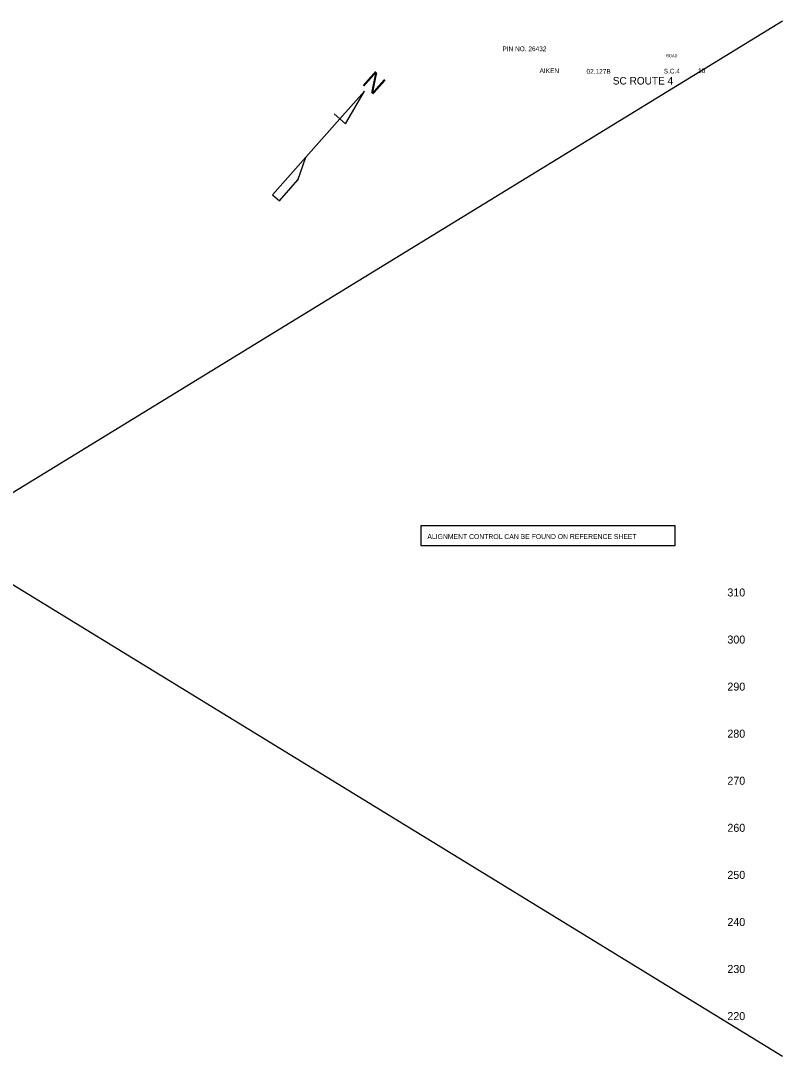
# Model space of a CAD drawing. Extents: x 49241 to 62599, y 49216 to 56011.
# Drawn here: x 51047 to 51856, y 53788 to 54888 of the extents above; entities that cross this region are included whole.
import ezdxf

# ---------------------------------------------------------------- set-up
doc = ezdxf.new("R2010")
doc.units = 0
for name, color, linetype in [('Level 1', 7, 'Continuous'), ('Level 2', 7, 'Continuous'), ('Level 24', 7, 'Continuous'), ('Level 25', 7, 'Continuous'), ('Level 42', 7, 'Continuous')]:
    doc.layers.add(name, color=color, linetype=linetype)

msp = doc.modelspace()

# ---------------------------------------------------------------- linework, layer by layer
at = {"layer": 'Level 1'}
for p, q in [((50060.6, 53787.8), (51856.5, 54887.8)), ((50060.6, 54887.8), (51856.5, 53787.8))]:
    msp.add_line(p, q, dxfattribs=at)
at = {"layer": 'Level 2'}
for p, q in [((51412.3, 54812.8), (51386.3, 54783.5)), ((51392.1, 54778.3), (51412.3, 54812.8)), ((51412.3, 54812.8), (51412.3, 54812.8)), ((51350.1, 54742.8), (51386.3, 54783.5)), ((51380.4, 54788.7), (51386.3, 54783.5)), ((51386.3, 54783.5), (51392.1, 54778.3)), ((51392.1, 54778.3), (51392.4, 54778.6)), ((51350.1, 54742.8), (51314.6, 54702.9)), ((51341.5, 54718.4), (51350.1, 54742.8)), ((51322, 54696.4), (51341.7, 54718.6)), ((51341.7, 54718.6), (51341.5, 54718.4)), ((51314.6, 54702.9), (51322, 54696.4))]:
    msp.add_line(p, q, dxfattribs=at)
at = {"layer": 'Level 25'}
msp.add_lwpolyline([(51472.8, 54351.4), (51742.2, 54351.4), (51742.2, 54330.1), (51472.8, 54330.1)], close=True, dxfattribs=at)

# ---------------------------------------------------------------- texts
at = {"layer": 'Level 2'}
msp.add_text('N', height=20, rotation=318.3667, dxfattribs=at).set_placement((51408.9, 54820.8))
at = {"layer": 'Level 24'}
for s, height, p in [('PIN NO. 26432', 5, (51559, 54855.4)), ('ROAD', 3, (51733, 54849)), ('AIKEN', 5, (51598.5, 54832.1)), ('02.127B', 5, (51648.4, 54831.4)), ('S.C.4', 5, (51730.4, 54831.7)), ('10', 5, (51766.9, 54832.2)), ('SC ROUTE 4', 8, (51676.3, 54820))]:
    msp.add_text(s, height=height, dxfattribs=at).set_placement(p)
at = {"layer": 'Level 25'}
msp.add_text('ALIGNMENT CONTROL CAN BE FOUND ON REFERENCE SHEET', height=5.25, dxfattribs=at).set_placement((51479.3, 54337.2))
at = {"layer": 'Level 42'}
for s, p in [('310', (51798.1, 54276.2)), ('300', (51798.1, 54226.2)), ('290', (51798.1, 54176.2)), ('280', (51798.1, 54126.2)), ('270', (51798.1, 54076.2)), ('260', (51798.1, 54026.2)), ('250', (51798.1, 53976.2)), ('240', (51798.1, 53926.2)), ('230', (51798.1, 53876.2)), ('220', (51798.1, 53826.2))]:
    msp.add_text(s, height=8.5, dxfattribs=at).set_placement(p)

doc.saveas('drawing.dxf')
